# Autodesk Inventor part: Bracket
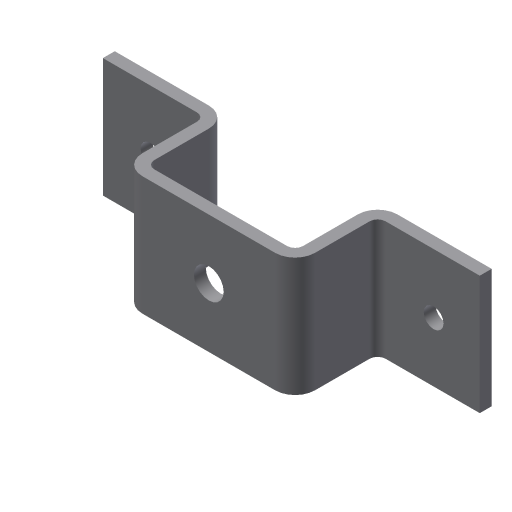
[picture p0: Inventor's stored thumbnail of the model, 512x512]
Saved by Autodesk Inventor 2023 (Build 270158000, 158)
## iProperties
Created: 2010-05
Part Number: Bracket
Document SubType Name: Modeling
Designer: CADSoft
Density: 1 g/cm^3
Material: Generic
Appearance: Default
Author: CADSoft
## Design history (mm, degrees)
sketch "Sketch1"
  geometry: L1 (-476.866, 0)-(-189.366, 0); L2 (-189.366, 0)-(-189.366, -208); L3 (-189.366, -208)-(185.634, -208); L4 (185.634, -208)-(185.634, 0); L5 (185.634, 0)-(473.134, 0); L6 (473.134, 0)-(473.134, -30); L7 (473.134, -30)-(215.634, -30); L8 (215.634, -30)-(215.634, -238); L9 (215.634, -238)-(-219.366, -238); L10 (-219.366, -238)-(-219.366, -30); L11 (-219.366, -30)-(-476.866, -30); L12 (-476.866, -30)-(-476.866, 0); 1 further point
  constraints: 24 end point, 8 parallel, 5 equal length, 1 collinear, 1 horizontal, 1 horizontal alignment, 1 perpendicular
  dimensions: "d0" = 950 distance between parallel lines of L6 L12; "d1" = 238 distance between parallel lines of L1 L9; "d2" = 30 distance of L5.end L6.end; "d3" = 30 distance between parallel lines of L9 L3; "d4" = 30 distance between parallel lines of L4 L8; "d5" = 435 distance of L8.end L9.end
extrude "Extrusion1" new body sketch "Sketch1" stored distance "d6" = 300; taper "d7" = 0 deg
fillet "Fillet1" dims "d8" = 20
fillet "Fillet2" dims "d9" = 50
hole "Hole1" diameter "d12" = 75; stored, may be unused: countersink angle "d16" = 90 deg, drill point angle "d18" = 118 deg; dims "d10" = 150, "d11" = 217.5, "d13" = 6, "d14" = 4, "d15" = 2, "d17" = 8
hole "Hole2" diameter "d21" = 50; stored, may be unused: countersink angle "d25" = 90 deg, drill point angle "d27" = 118 deg; dims "d19" = 150, "d20" = 120, "d22" = 6, "d23" = 4, "d24" = 2, "d26" = 8
mirror "Mirror1"
body "Solid1"
